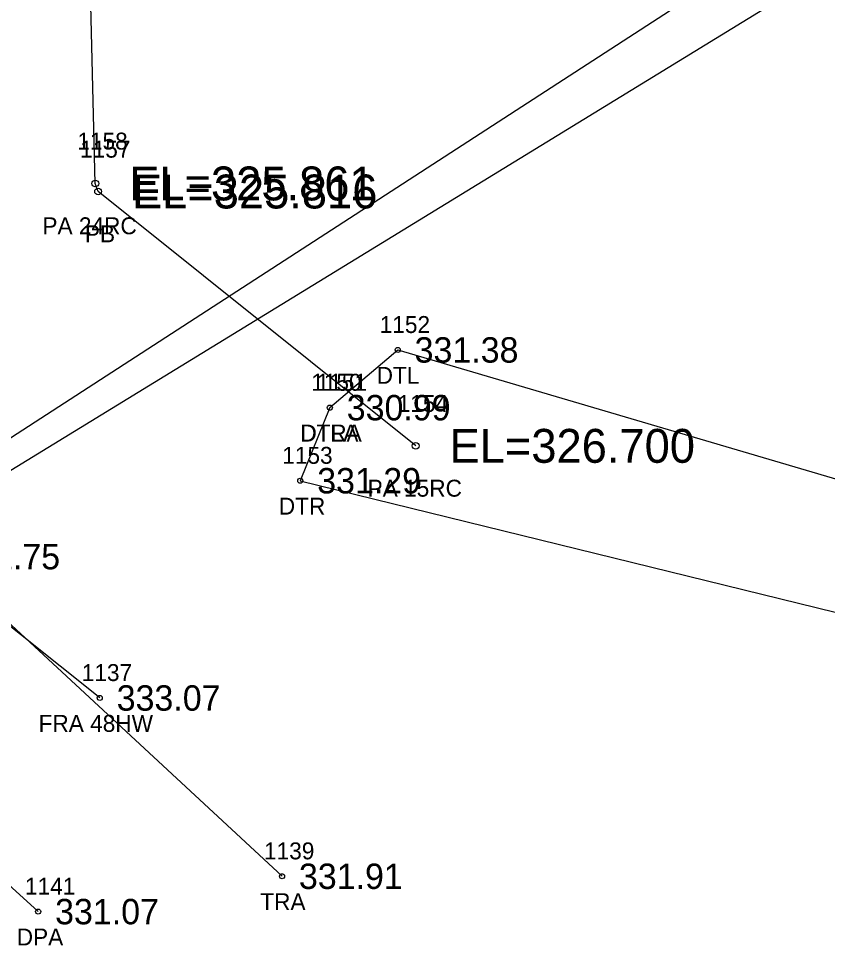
# Model space of a CAD drawing. Extents: x 2231119 to 2232595, y 1035731 to 1037094.
# Drawn here: x 2231738 to 2231785.8, y 1036470.9 to 1036525.6 of the extents above; entities that cross this region are included whole.
import ezdxf

# ---------------------------------------------------------------- set-up
doc = ezdxf.new("R2010")
doc.units = 0
for name, color, linetype in [('RD_EX_DR_Pipe', 7, 'Continuous'), ('RD_EX_DR_Pipe_txCode', 7, 'Continuous'), ('RD_EX_Driveway', 7, 'Continuous'), ('RD_EX_Driveway_txCode', 7, 'Continuous'), ('RD_EX_Fence_Other', 7, 'Continuous'), ('RD_EX_Fence_Other_txCode', 7, 'Continuous'), ('RD_EX_H2O', 7, 'Continuous'), ('RD_EX_H2O_txCode', 7, 'Continuous'), ('RD_EX_TX_Driveway_ELEV', 7, 'Continuous'), ('RD_EX_TX_DV_Prop_ELEV', 7, 'Continuous'), ('RD_EX_TX_Fence_Other_ELEV', 7, 'Continuous'), ('RD_EX_TX_H2O_ELEV', 7, 'Continuous'), ('RD_EX_TX_VEG_ELEV', 7, 'Continuous'), ('RD_EX_VEG', 7, 'Continuous'), ('RD_EX_VEG_txCode', 7, 'Continuous'), ('RD_SMD_Locator', 7, 'Continuous'), ('RD_TX_Pipe_ElevEX', 7, 'Continuous')]:
    doc.layers.add(name, color=color, linetype=linetype)

msp = doc.modelspace()

# ---------------------------------------------------------------- linework, layer by layer
at = {"layer": 'RD_EX_DR_Pipe'}
msp.add_lwpolyline([(2231761.489, 1036500.401), (2231742.724, 1036515.422), (2231742.562, 1036515.898), (2231741.252, 1036569.435)], dxfattribs=at)
at = {"layer": 'RD_EX_Driveway'}
msp.add_lwpolyline([(2231739.186, 1036472.896), (2231720.317, 1036490.052), (2231706.071, 1036512.594)], dxfattribs=at)
at = {"layer": 'RD_EX_Fence_Other'}
msp.add_lwpolyline([(2231742.824, 1036485.512), (2231730.988, 1036494.959), (2231789.882, 1036531.024), (2231876.814, 1036583.892), (2231964.372, 1036635.233), (2232046.176, 1036684.795), (2232133.572, 1036734.398), (2232210.599, 1036793.489), (2232301.782, 1036835.026)], dxfattribs=at)
at = {"layer": 'RD_EX_H2O'}
for points in [[(2231756.416, 1036502.657), (2231760.426, 1036506.067), (2231796.459, 1036495.468)], [(2231756.416, 1036502.657), (2231754.67, 1036498.342), (2231795.01, 1036488.436)]]:
    msp.add_lwpolyline(points, dxfattribs=at)
at = {"layer": 'RD_EX_VEG'}
msp.add_lwpolyline([(2231753.591, 1036474.982), (2231730.547, 1036496.345), (2231788.451, 1036533.865), (2231871.454, 1036588.786), (2231958.943, 1036639.514), (2232040.643, 1036687.925), (2232130.591, 1036740.479), (2232213.065, 1036784.391), (2232299.538, 1036835.553)], dxfattribs=at)
at = {"layer": 'RD_SMD_Locator'}
for centre, radius in [((2231742.562, 1036515.898), 0.2), ((2231742.724, 1036515.422), 0.2), ((2231760.426, 1036506.067), 0.15), ((2231756.416, 1036502.657), 0.15), ((2231756.416, 1036502.657), 0.15), ((2231761.489, 1036500.401), 0.2), ((2231754.67, 1036498.342), 0.15), ((2231742.824, 1036485.512), 0.15), ((2231753.591, 1036474.982), 0.15), ((2231739.186, 1036472.896), 0.15)]:
    msp.add_circle(centre, radius, dxfattribs=at)

# ---------------------------------------------------------------- texts
at = {"layer": 'RD_EX_DR_Pipe_txCode'}
for s, p in [('1158', (2231741.499, 1036517.898)), ('1157', (2231741.661, 1036517.422)), ('PA 24RC', (2231739.436, 1036512.898)), ('PB', (2231741.944, 1036512.422)), ('1154', (2231760.426, 1036502.401)), ('PA 15RC', (2231758.647, 1036497.401))]:
    msp.add_text(s, height=1, dxfattribs=at).set_placement(p)
at = {"layer": 'RD_EX_Driveway_txCode'}
for s, p in [('1141', (2231738.406, 1036473.896)), ('DPA', (2231737.918, 1036470.896))]:
    msp.add_text(s, height=1, dxfattribs=at).set_placement(p)
at = {"layer": 'RD_EX_Fence_Other_txCode'}
for s, p in [('1137', (2231741.761, 1036486.512)), ('FRA 48HW', (2231739.209, 1036483.512))]:
    msp.add_text(s, height=1, dxfattribs=at).set_placement(p)
at = {"layer": 'RD_EX_H2O_txCode'}
for s, p in [('1152', (2231759.363, 1036507.067)), ('DTL', (2231759.182, 1036504.067)), ('1150', (2231755.313, 1036503.657)), ('1151', (2231755.636, 1036503.657)), ('DTRA', (2231754.66, 1036500.657)), ('DTLA', (2231754.684, 1036500.657)), ('1153', (2231753.607, 1036499.342)), ('DTR', (2231753.402, 1036496.342))]:
    msp.add_text(s, height=1, dxfattribs=at).set_placement(p)
at = {"layer": 'RD_EX_TX_Driveway_ELEV'}
msp.add_text('331.07', height=1.5, dxfattribs=at).set_placement((2231740.186, 1036472.146))
at = {"layer": 'RD_EX_TX_DV_Prop_ELEV'}
msp.add_text('331.75', height=1.5, dxfattribs=at).set_placement((2231734.346, 1036493.109))
at = {"layer": 'RD_EX_TX_Fence_Other_ELEV'}
msp.add_text('333.07', height=1.5, dxfattribs=at).set_placement((2231743.824, 1036484.762))
at = {"layer": 'RD_EX_TX_H2O_ELEV'}
for s, p in [('331.38', (2231761.426, 1036505.317)), ('330.99', (2231757.416, 1036501.907)), ('330.99', (2231757.416, 1036501.907)), ('331.29', (2231755.67, 1036497.592))]:
    msp.add_text(s, height=1.5, dxfattribs=at).set_placement(p)
at = {"layer": 'RD_EX_TX_VEG_ELEV'}
msp.add_text('331.91', height=1.5, dxfattribs=at).set_placement((2231754.591, 1036474.232))
at = {"layer": 'RD_EX_VEG_txCode'}
for s, p in [('1139', (2231752.528, 1036475.982)), ('TRA', (2231752.308, 1036472.982))]:
    msp.add_text(s, height=1, dxfattribs=at).set_placement(p)
at = {"layer": 'RD_TX_Pipe_ElevEX'}
for s, p in [('EL=325.861', (2231744.562, 1036514.898)), ('EL=325.816', (2231744.724, 1036514.422)), ('EL=326.700', (2231763.489, 1036499.401))]:
    msp.add_text(s, height=2, dxfattribs=at).set_placement(p)

doc.saveas('drawing.dxf')
